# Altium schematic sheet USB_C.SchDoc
size A4; Organization: Altium Limited; Address1: L3, 12a Rodborough Rd; Address2: Frenchs Forest; Address3: NSW; Address4: Australia 2086
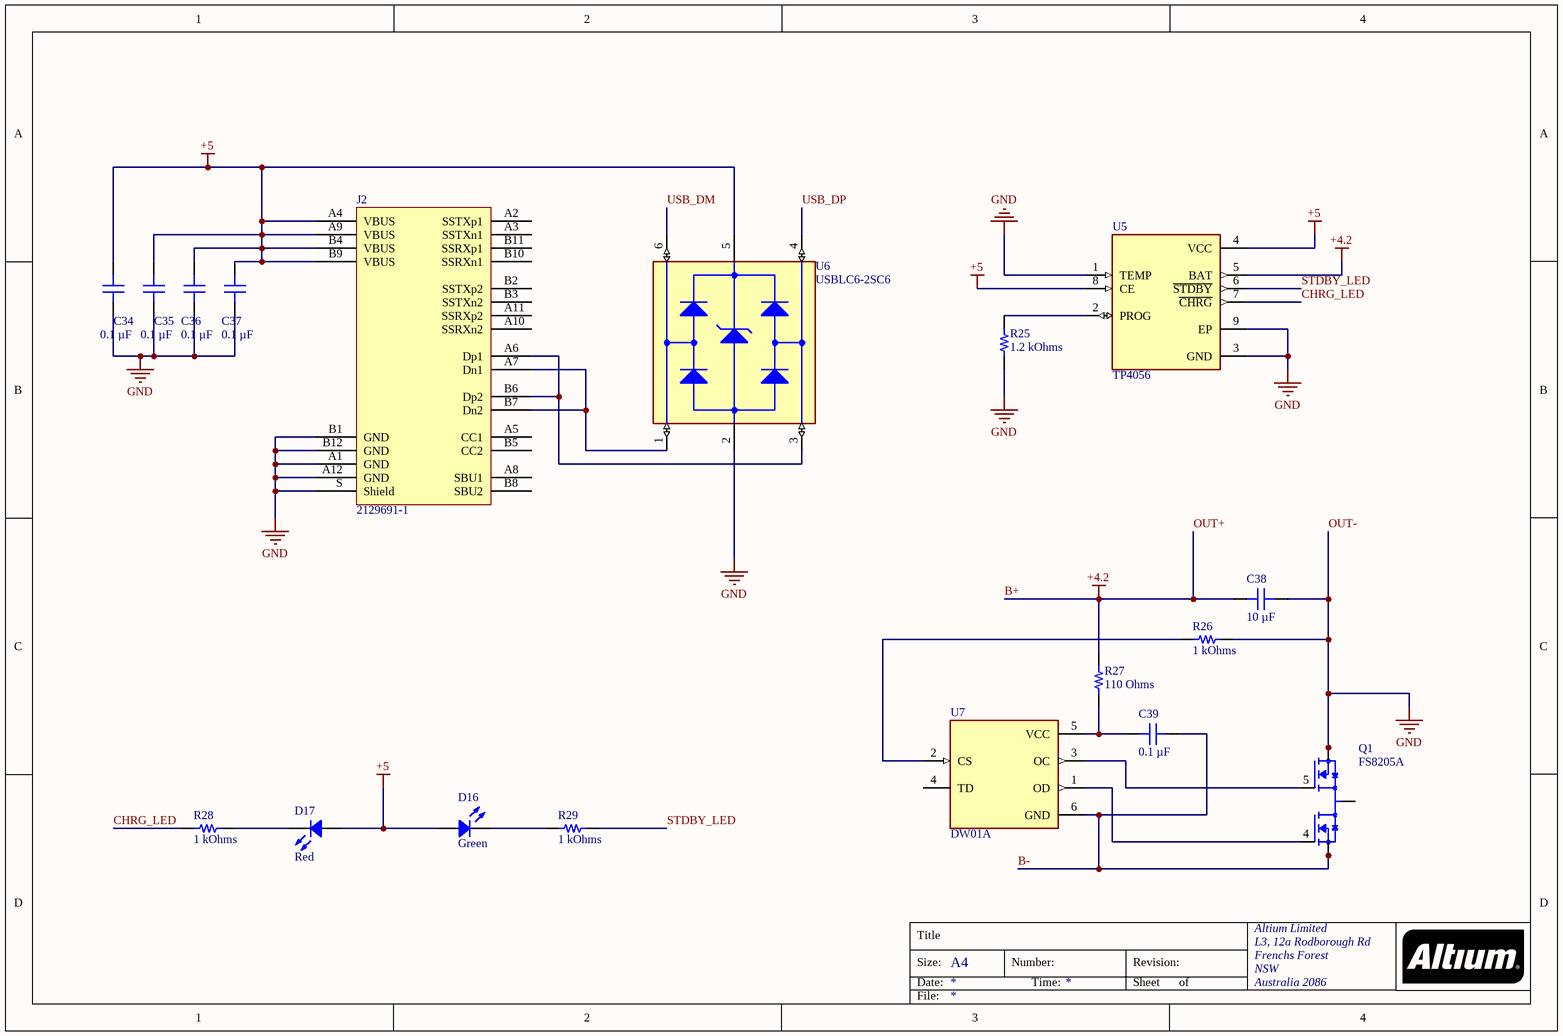
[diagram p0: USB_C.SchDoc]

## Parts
C34  0.1 µF  [CAP 0402_1005]
C35  0.1 µF  [CAP 0402_1005]
C36  0.1 µF  [CAP 0402_1005]
C37  0.1 µF  [CAP 0402_1005]
C38  10 µF  [CAP 0402_1005]
C39  0.1 µF  [CAP 0402_1005]
D16  Green  [LED 0402_1005 GREEN]
D17  Red  [LED 0402_1005 RED]
J2  2129691-1  [TE USB-C 2129691-1]
Q1  FS8205A  [SOP65P640X120-8N]
R25  1.2 kOhms  [RES 0402_1005]
R26  1 kOhms  [RES 0402_1005]
R27  110 Ohms  [RES 0402_1005]
R28  1 kOhms  [RES 0402_1005]
R29  1 kOhms  [RES 0402_1005]
U5  TP4056  [SOP127P600X175-9N]
U6  USBLC6-2SC6  [SOT95P280X145-6N]
U7  DW01A  [SOT95P280X145-6N]

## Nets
+5: C34.1 C35.1 C36.1 C37.1 D16.1 D17.1 J2.A4(VBUS) J2.A9(VBUS) J2.B4(VBUS) J2.B9(VBUS) U5.4(VCC) U5.8(CE) U6.5(VBUS)
B+: C38.1 R27.2 U5.5(BAT)  [also labelled +4.2, OUT+]
OUT-: C34.2 C35.2 C36.2 C37.2 C38.2 J2.A1(GND) J2.A12(GND) J2.B1(GND) J2.B12(GND) J2.S(Shield) Q1.6(S2) Q1.7(S2) R25.1 R26.2 U5.1(TEMP) U5.3(GND) U5.9(EP) U6.2(GND)  [also labelled GND]
B-: C39.2 Q1.2(S1) Q1.3(S1) U7.6(GND)
CHRG_LED: R28.1 U5.7(~{CHRG})
STDBY_LED: R29.2 U5.6(~{STDBY})
USB_DM: U6.6(I/O1_OUT)
USB_DP: U6.4(I/O2_OUT)
NetC39_1: C39.1 R27.1 U7.5(VCC)
NetD16_2: D16.2 R29.1
NetD17_2: D17.2 R28.2
NetJ2_A6: J2.A6(Dp1) J2.B6(Dp2) U6.3(I/O2_IN)
NetJ2_A7: J2.A7(Dn1) J2.B7(Dn2) U6.1(I/O1_IN)
NetQ1_1: Q1.1(D12) Q1.8(D12)
NetQ1_4: Q1.4(G1) U7.1(OD)
NetQ1_5: Q1.5(G2) U7.3(OC)
NetR25_2: R25.2 U5.2(PROG)
NetR26_1: R26.1 U7.2(CS)

Not connected (* = marked no-connect by the designer): J2 A2(SSTXp1) A3(SSTXn1) A5(CC1) A8(SBU1) A10(SSRXn2) A11(SSRXp2) B2(SSTXp2) B3(SSTXn2) B5(CC2) B8(SBU2) B10(SSRXn1) B11(SSRXp1); U7 4(TD)

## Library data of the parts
C34-C37 C39 = KGM05AR71A104KH: CAP CER 0.1UF 10V X7R 0402; manufacturer: KYOCERA AVX; Tolerance: ±10%
C38 = CL05A106MP8NUB8: CAP CER 10UF 10V X5R 0402; manufacturer: Samsung Electro-Mechanics; Tolerance: ±20%
D16 = 150040GS73240: LED GREEN CLEAR 0402 SMD; Manufacturer: Würth Elektronik; Configuration: Standard; Current - Test: 20mA; Lens Color: Colorless; Lens Size: 1.00mm x 0.50mm; Lens Style: Rectangle with Flat Top; Millicandela Rating: 800mcd; Viewing Angle: 120°; Voltage - Forward (Vf) (Typ): 3.2V; Wavelength - Dominant: 525nm; Wavelength - Peak: 515nm
D17 = 150040SS73220: LED RED CLEAR 0402 SMD; Manufacturer: Würth Elektronik; Configuration: 0402; Current - Test: 20mA; Lens Color: Colorless; Lens Size: 1.00mm x 0.50mm; Lens Style: Rectangle with Flat Top; Millicandela Rating: 90mcd; Viewing Angle: 120°; Voltage - Forward (Vf) (Typ): 2V; Wavelength - Dominant: 630nm; Wavelength - Peak: 645nm
J2 = 2129691-1: CONN RCPT USB3.1 TYPEC 24POS SMD; Manufacturer: TE Connectivity AMP Connectors; Connector Type: USB - C (Type - C); Current Rating (Amps): 0.25A, 1.25A, 5A; Gender: Receptacle; Mating Cycles: 10000; Number of Contacts: 24; Number of Ports: 1; Specifications: USB 3.1 (USB 3.1 Gen 2, Superspeed+); Voltage - Rated: 30V
Q1 = FS8205A: N/A; MF: Fortune Semiconductor
R25 = ERJ-2RKF1201X: RES SMD 1.2K OHM 1% 1/10W 0402; Manufacturer: Panasonic Electronic Components; Power (Watts): 0.1W, 1/10W; Temperature Coefficient: ±100ppm/°C
R26 = RK73H1ERTTP1001F: RES 1K OHM 1% 1/10W 0402; Manufacturer: KOA Speer Electronics, Inc.; Power (Watts): 0.1W, 1/10W; Temperature Coefficient: ±100ppm/°C
R27 = RK73H1ETTP1100F: RES 110 OHM 1% 1/10W 0402; Manufacturer: KOA Speer Electronics, Inc.; Power (Watts): 0.1W, 1/10W; Temperature Coefficient: ±100ppm/°C
R28 R29 = RK73G1ETTP1001D: RES 1K OHM 0.5% 1/10W 0402; Manufacturer: KOA Speer Electronics, Inc.; Power (Watts): 0.1W, 1/10W; Temperature Coefficient: ±50ppm/°C
U5 = TP4056: Complete single cell Li-Ion battery with a constant current / constant voltage linear charger; MF: NanJing Top Power ASIC Corp.
U6 = USBLC6-2SC6: 17V Clamp 5A (8/20Âµs) Ipp Tvs Diode Surface Mount SOT-23-6; MF: STMicroelectronics
U7 = DW01A: One Cell Lithium-ion/Polymer Battery Protection IC; MF: Fortune Semiconductor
